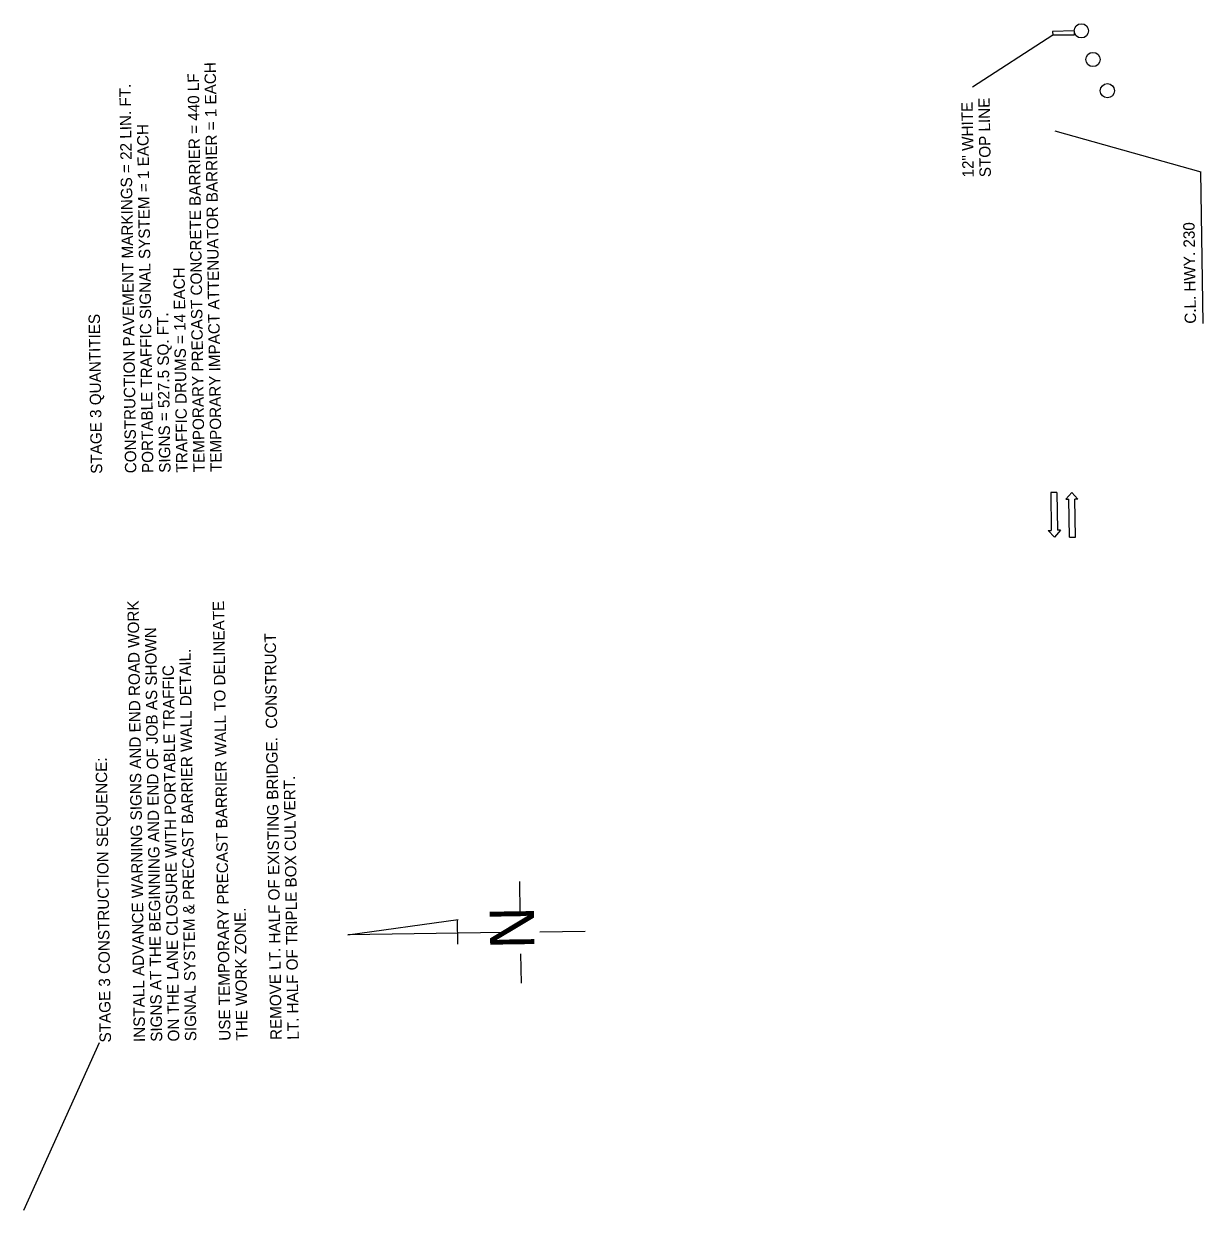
# Model space of a CAD drawing. Extents: x 1770018 to 1773492, y 718230 to 729141.
# Drawn here: x 1770253 to 1770875, y 725977 to 726602 of the extents above; entities that cross this region are included whole.
import ezdxf

# ---------------------------------------------------------------- set-up
doc = ezdxf.new("R2010")
doc.units = 0
for name, color, linetype in [('Default', 7, 'Continuous'), ('R_Border Notes', 7, 'Continuous'), ('R_Dimension', 7, 'Continuous'), ('R_Draft', 7, 'Continuous'), ('R_Horz Alg Annot', 7, 'Continuous'), ('R_MOT', 7, 'Continuous')]:
    doc.layers.add(name, color=color, linetype=linetype)

msp = doc.modelspace()

# ---------------------------------------------------------------- linework, layer by layer
at = {"layer": 'Default'}
for p, q in [((1770806.81, 726598.55), (1770795.45, 726598.29)), ((1770806.81, 726598.55), (1770795.45, 726598.29)), ((1770795.45, 726598.29), (1770795.5, 726596.29)), ((1770806.92, 726596.55), (1770806.88, 726597.84)), ((1770806.92, 726596.55), (1770795.5, 726596.29)), ((1770795.5, 726596.29), (1770806.92, 726596.55)), ((1770796.65, 726545.93), (1770873.58, 726524.34)), ((1770874.81, 726444.35), (1770873.58, 726524.34))]:
    msp.add_line(p, q, dxfattribs=at)
msp.add_arc((1770810.56, 726598.6), 3.75, 180.38409, 191.34582, dxfattribs=at)
at = {"layer": 'R_Border Notes'}
for p, q in [((1770797.61, 726355.35), (1770794.41, 726355.3)), ((1770794.41, 726355.3), (1770794.72, 726335.32)), ((1770797.61, 726355.35), (1770797.92, 726335.37)), ((1770802.36, 726351.75), (1770805.5, 726355.31)), ((1770805.5, 726355.31), (1770808.76, 726351.85)), ((1770802.36, 726351.75), (1770803.96, 726351.77)), ((1770804.26, 726331.79), (1770803.96, 726351.77)), ((1770808.76, 726351.85), (1770807.16, 726351.82)), ((1770807.46, 726331.84), (1770807.16, 726351.82)), ((1770793.12, 726335.29), (1770794.72, 726335.32)), ((1770796.37, 726331.84), (1770793.12, 726335.29)), ((1770799.52, 726335.39), (1770796.37, 726331.84)), ((1770799.52, 726335.39), (1770797.92, 726335.37)), ((1770804.26, 726331.79), (1770807.46, 726331.84))]:
    msp.add_line(p, q, dxfattribs=at)
at = {"layer": 'R_Dimension'}
msp.add_line((1770795.5, 726596.29), (1770753.29, 726568.88), dxfattribs=at)
at = {"layer": 'R_Draft'}
for p, q in [((1770514.91, 726133.76), (1770514.65, 726150.24)), ((1770424.13, 726122.09), (1770482.2, 726130.26)), ((1770481.97, 726117.33), (1770481.77, 726130.27)), ((1770505.48, 726123.34), (1770424.13, 726122.09)), ((1770549.11, 726124.01), (1770525.19, 726123.65)), ((1770515.48, 726096.74), (1770515.24, 726112.17))]:
    msp.add_line(p, q, dxfattribs=at)
at = {"layer": 'R_MOT'}
msp.add_line((1770253.27, 725977.01), (1770293.26, 726065.39), dxfattribs=at)
for centre in [(1770810.55, 726598.6), (1770816.7, 726583.49), (1770824.28, 726567.05)]:
    msp.add_circle(centre, 3.75, dxfattribs=at)

# ---------------------------------------------------------------- texts
at = {"layer": 'R_Dimension'}
for s, p in [('12" WHITE', (1770753.91, 726521.38)), ('STOP LINE', (1770762.91, 726521.52))]:
    msp.add_text(s, height=6, rotation=90.88269, dxfattribs=at).set_placement(p)
at = {"layer": 'R_Draft'}
for s, height, rotation, p in [('TEMPORARY IMPACT ATTENUATOR BARRIER = 1 EACH', 6, 90.84663, (1770357.63, 726366.14)), ('TEMPORARY PRECAST CONCRETE BARRIER = 440 LF', 6, 90.84663, (1770348.64, 726366.01)), ('CONSTRUCTION PAVEMENT MARKINGS = 22 LIN. FT.', 6, 90.84663, (1770312.64, 726365.48)), ('PORTABLE TRAFFIC SIGNAL SYSTEM = 1 EACH', 6, 90.84663, (1770321.64, 726365.61)), ('TRAFFIC DRUMS = 14 EACH', 6, 90.84663, (1770339.64, 726365.88)), ('STAGE 3 QUANTITIES', 6, 90.84663, (1770294.64, 726365.21)), ('SIGNS = 527.5 SQ. FT.', 6, 90.84663, (1770330.64, 726365.74)), ('INSTALL ADVANCE WARNING SIGNS AND END ROAD WORK ', 6, 90.84663, (1770317.26, 726065.74)), ('USE TEMPORARY PRECAST BARRIER WALL TO DELINEATE', 6, 90.84663, (1770362.25, 726066.41)), ('SIGNS AT THE BEGINNING AND END OF JOB AS SHOWN ', 6, 90.84663, (1770326.26, 726065.87)), ('REMOVE LT. HALF OF EXISTING BRIDGE.  CONSTRUCT', 6, 90.84663, (1770389.25, 726066.8)), ('SIGNAL SYSTEM & PRECAST BARRIER WALL DETAIL.', 6, 90.84663, (1770344.25, 726066.14)), ('ON THE LANE CLOSURE WITH PORTABLE TRAFFIC ', 6, 90.84663, (1770335.26, 726066.01)), ('STAGE 3 CONSTRUCTION SEQUENCE:', 6, 90.84663, (1770299.26, 726065.48)), ('LT. HALF OF TRIPLE BOX CULVERT. ', 6, 90.84663, (1770398.25, 726066.94)), ('THE WORK ZONE. ', 6, 90.84663, (1770371.25, 726066.54)), ('N', 23.27, 90.88269, (1770522.37, 726114.78))]:
    msp.add_text(s, height=height, rotation=rotation, dxfattribs=at).set_placement(p)
at = {"layer": 'R_Horz Alg Annot'}
msp.add_text('C.L. HWY. 230', height=6, rotation=90.88065, dxfattribs=at).set_placement((1770871.04, 726444.29))

doc.saveas('drawing.dxf')
